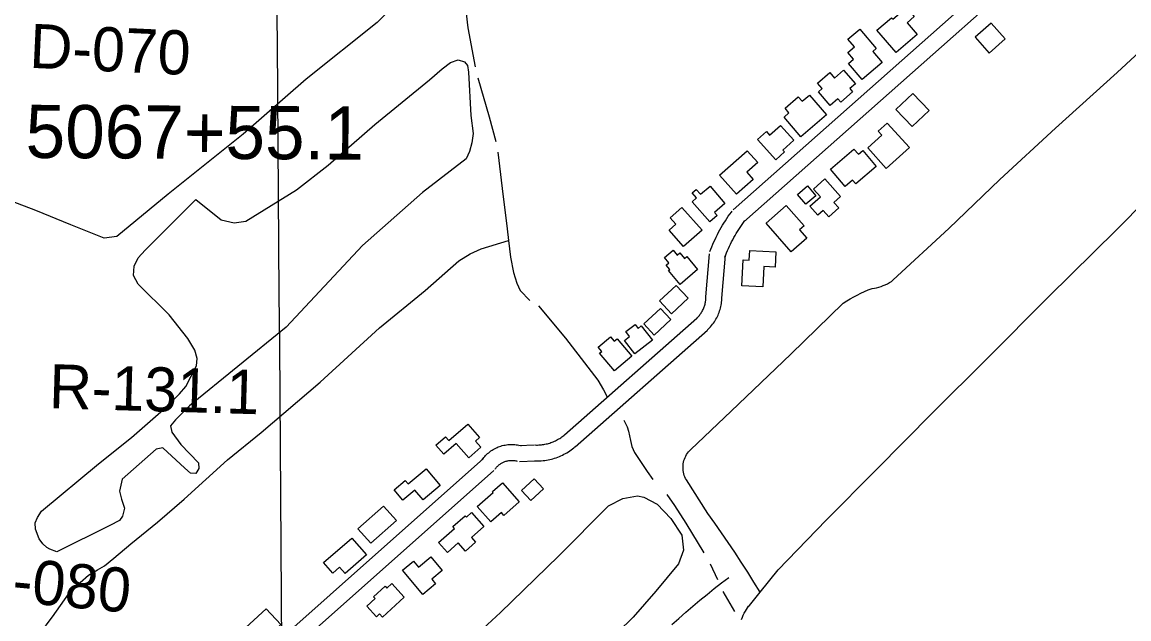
# Model space of a CAD drawing. Extents: x 3535183 to 3573198, y 534952 to 560562.
# Drawn here: x 3554620 to 3556701, y 553117 to 554240 of the extents above; entities that cross this region are included whole.
import ezdxf

# ---------------------------------------------------------------- set-up
doc = ezdxf.new("R2010")
doc.units = 0
for name, color, linetype in [('V-BLDG-OTLN', 7, 'Continuous'), ('V-DTCH-CNTR', 7, 'Continuous'), ('V-GRID-MAJR', 7, 'Continuous'), ('V-RIVR-RANG-IDEN', 7, 'Continuous'), ('V-ROAD-CNTR', 7, 'Continuous'), ('V-SITE-VEGE', 7, 'Continuous'), ('V-SURV-IDEN', 7, 'Continuous'), ('V-TOPO-SHOR', 7, 'Continuous')]:
    doc.layers.add(name, color=color, linetype=linetype)

msp = doc.modelspace()

# ---------------------------------------------------------------- linework, layer by layer
at = {"layer": 'V-BLDG-OTLN'}
for points in [[(3556284.02, 554238.5), (3556302.765, 554216.926), (3556263.6550000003, 554182.938), (3556227.417, 554224.637), (3556254.639, 554248.2930000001), (3556257.267, 554245.273), (3556282.752, 554267.42), (3556297.615, 554250.313)], [(3556195.071, 554226.716), (3556226.058, 554190.589), (3556219.508, 554184.971), (3556237.309, 554164.215), (3556199.964, 554132.186), (3556174.102, 554162.341), (3556183.361, 554170.283), (3556172.812, 554182.581), (3556185.267, 554193.264), (3556172.8910000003, 554207.694)], [(3556442.0900774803, 554238.2794971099), (3556412.156137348, 554211.7455501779), (3556438.689084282, 554181.812610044), (3556468.6230244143, 554208.345556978)], [(3556153.8310000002, 554095.8420000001), (3556139.536, 554083.345), (3556117.358, 554108.714), (3556124.6750000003, 554115.1140000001), (3556115.722, 554125.354), (3556138.594, 554145.353), (3556147.816, 554134.806), (3556164.697, 554149.5650000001), (3556186.92, 554124.15), (3556176.34, 554114.897), (3556181.698, 554108.773), (3556159.498, 554089.362)], [(3556100.503, 554102.8200000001), (3556132.529, 554065.393), (3556084.5100000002, 554024.306), (3556052.768, 554061.399), (3556062.0500000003, 554069.341), (3556054.615, 554078.029), (3556079.669, 554099.465), (3556086.818, 554091.109)], [(3556325.482, 554073.56), (3556293.775, 554043.358), (3556263.159, 554075.502), (3556294.864, 554105.701)], [(3556045.93, 554045.808), (3556071.186, 554017.738), (3556050.6750000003, 553999.283), (3556053.815, 553995.7980000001), (3556037.482, 553981.099), (3556003.0470000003, 554019.372), (3556019.517, 554034.193), (3556025.558, 554027.478)], [(3556246.947, 554050.082), (3556288.347, 554003.8150000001), (3556244.705, 553964.764), (3556210.071, 554003.4670000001), (3556236.588, 554027.1950000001), (3556229.824, 554034.757)], [(3555931.563, 553952.067), (3555983.546, 553998.153), (3556003.542, 553975.596), (3555983.089, 553957.463), (3555994.863, 553944.184), (3555963.336, 553916.231)], [(3556200.691, 553998.278), (3556226.211, 553968.387), (3556187.827, 553935.6190000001), (3556181.79, 553942.693), (3556167.786, 553930.7390000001), (3556139.91, 553963.392), (3556184.295, 554001.284), (3556192.691, 553991.446)], [(3555913.6350000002, 553931.501), (3555941.756, 553899.013), (3555921.952, 553881.871), (3555926.978, 553876.067), (3555913.144, 553864.093), (3555880.185, 553902.169), (3555888.23, 553909.13), (3555880.1010000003, 553918.52), (3555887.873, 553925.25), (3555895.815, 553916.077)], [(3556112.59, 553913.142), (3556093.878, 553897.258), (3556078.059, 553915.897), (3556096.771, 553931.781)], [(3556108.16, 553925.885), (3556129.732, 553944.89), (3556158.877, 553911.8150000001), (3556146.507, 553900.916), (3556155.852, 553890.309), (3556137.029, 553873.726), (3556126.631, 553885.525), (3556116.434, 553876.54), (3556101.244, 553893.78), (3556121.061, 553911.24)], [(3555860.8680000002, 553891.139), (3555898.6210000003, 553848.514), (3555863.92, 553817.777), (3555836.585, 553848.638), (3555849.129, 553859.747), (3555838.7090000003, 553871.511)], [(3556018.994, 553861.557), (3556056.684, 553894.884), (3556090.603, 553856.529), (3556082.102, 553849.011), (3556095.614, 553833.731), (3556066.4280000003, 553807.92)], [(3555869.794, 553798.807), (3555890.364, 553774.376), (3555857.282, 553746.523), (3555835.4450000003, 553772.461), (3555838.115, 553774.71), (3555831.205, 553782.9180000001), (3555836.268, 553787.18), (3555827.773, 553797.273), (3555844.239, 553811.135), (3555852.076, 553801.825), (3555856.953, 553805.932), (3555865.79, 553795.436)], [(3555988.348, 553810.028), (3556037.252, 553807.73), (3556035.911, 553779.1680000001), (3556014.872, 553780.157), (3556013.078, 553741.95), (3555973.6350000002, 553743.803), (3555975.927, 553792.554), (3555987.502, 553792.009)], [(3555841.537, 553691.356), (3555818.886, 553715.527), (3555850, 553744.684), (3555872.651, 553720.514)], [(3555808.54, 553651.2710000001), (3555789.012, 553672.322), (3555820.398, 553701.434), (3555839.926, 553680.385)], [(3555772.366, 553615.7930000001), (3555752.576, 553641.004), (3555762.325, 553648.657), (3555755.247, 553657.6730000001), (3555772.735, 553671.4), (3555778.67, 553663.837), (3555784.382, 553668.3200000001), (3555805.3140000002, 553641.653)], [(3555739.0470000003, 553644.375), (3555766.648, 553611.365), (3555733.8370000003, 553583.93), (3555706.132, 553617.067), (3555710.072, 553620.36), (3555703.432, 553628.302), (3555726.661, 553647.724), (3555733.403, 553639.656)], [(3555422.596, 553452.596), (3555458.1720000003, 553483.554), (3555480.225, 553458.212), (3555472.736, 553451.693), (3555482.728, 553440.212), (3555460.007, 553420.443), (3555436.506, 553447.452), (3555413.077, 553427.066), (3555398.446, 553443.88), (3555416.508, 553459.594)], [(3555346.323, 553371.358), (3555379.7600000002, 553399.5430000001), (3555406.315, 553368.0380000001), (3555374.251, 553341.015), (3555358.6580000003, 553359.517), (3555336.199, 553340.589), (3555319.772, 553360.082), (3555340.84, 553377.863)], [(3555555.075, 553337.218), (3555526.24, 553311.976), (3555521.4590000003, 553317.438), (3555501.483, 553299.951), (3555476.18, 553328.856), (3555506.1240000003, 553355.073), (3555504.535, 553356.887), (3555523.401, 553373.402)], [(3555600.549, 553361.696), (3555576.911, 553339.837), (3555559.403, 553358.7710000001), (3555583.041, 553380.63)], [(3555324.014, 553302.482), (3555275.714, 553259.558), (3555251.646, 553286.639), (3555299.9560000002, 553329.554)], [(3555403.319, 553260.912), (3555433.455, 553287.456), (3555430.336, 553290.995), (3555453.339, 553311.258), (3555455.7430000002, 553308.528), (3555465.482, 553317.105), (3555488.591, 553290.872), (3555465.309, 553270.363), (3555472.975, 553261.661), (3555453.89, 553244.849), (3555440.367, 553260.203), (3555419.858, 553242.138)], [(3555187.123, 553223.355), (3555240.359, 553269.403), (3555267.915, 553237.544), (3555227.578, 553202.654), (3555217.223, 553214.627), (3555204.325, 553203.469)], [(3555365.924, 553214.604), (3555389.046, 553233.8640000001), (3555410.419, 553208.206), (3555390.6, 553191.702), (3555397.867, 553182.975), (3555373.727, 553162.87), (3555335.563, 553208.688), (3555356.397, 553226.042)], [(3555338.94, 553158.1680000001), (3555297.898, 553120.6950000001), (3555292.3170000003, 553126.807), (3555286.365, 553121.373), (3555268.3140000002, 553141.143), (3555284.137, 553155.589), (3555281.268, 553158.735), (3555302.9930000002, 553178.572), (3555306.037, 553175.238), (3555315.482, 553183.862)], [(3555052.648, 553056.888), (3555025.565, 553086.33), (3555079.554, 553135.996), (3555106.637, 553106.554)]]:
    msp.add_lwpolyline(points, close=True, dxfattribs=at)
at = {"layer": 'V-DTCH-CNTR'}
for points in [[(3555986.251, 553140.93), (3555987.644, 553142.748), (3556007.823, 553167.609), (3556041.703, 553209.343), (3556131.9990000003, 553302.99), (3556225.414, 553397.03), (3556333.2290000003, 553505.897), (3556433.262, 553605.7930000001), (3556550.029, 553722.856), (3556677.699, 553849.286), (3556791.3510000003, 553964.006), (3556875.81, 554051.8), (3556968.443, 554145.84), (3557082.875, 554262.511), (3557214.992, 554385.362), (3557325.5300000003, 554497.351), (3557493.6750000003, 554666.313), (3557606.16, 554781.421), (3557708.529, 554882.876), (3557851.377, 555024.526), (3557973.2, 555149.78), (3558100.09, 555276.209)], [(3556007.823, 553167.609), (3555996.221, 553186.524), (3555984.4280000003, 553205.323), (3555972.454, 553224.005), (3555960.291, 553242.568), (3555947.9450000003, 553261.006), (3555935.418, 553279.321), (3555922.708, 553297.513), (3555909.818, 553315.577), (3555869.208, 553378.657), (3555867.719, 553381.416), (3555866.421, 553384.269), (3555865.315, 553387.202), (3555864.411, 553390.204), (3555863.711, 553393.26), (3555863.219, 553396.354), (3555862.937, 553399.477), (3555862.863, 553402.611), (3555863.002, 553405.7440000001), (3555863.353, 553408.859), (3555863.912, 553411.9450000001), (3555864.6780000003, 553414.987), (3555865.646, 553417.969), (3555866.8140000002, 553420.879), (3555868.174, 553423.705), (3555869.722, 553426.433), (3555871.45, 553429.05), (3555873.3510000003, 553431.545), (3555875.413, 553433.906), (3555877.631, 553436.1240000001), (3555953.223, 553507.759), (3556065.715, 553615.072), (3556164.1920000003, 553711.457), (3556170.614, 553715.512), (3556177.145, 553719.3910000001), (3556183.781, 553723.0920000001), (3556190.512, 553726.608), (3556197.338, 553729.9400000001), (3556204.254, 553733.086), (3556211.25, 553736.041), (3556218.326, 553738.804), (3556222.613, 553739.447), (3556226.856, 553740.314), (3556231.051, 553741.399), (3556235.183, 553742.702), (3556239.2430000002, 553744.2170000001), (3556243.218, 553745.944), (3556247.097, 553747.873), (3556250.869, 553750.001), (3556254.5270000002, 553752.323), (3556258.058, 553754.834), (3556362.77, 553851.6140000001), (3556458.524, 553943.709), (3556563.234, 554040.491), (3556679.237, 554145.469), (3556797.5700000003, 554254.738)]]:
    msp.add_lwpolyline(points, dxfattribs=at)
at = {"layer": 'V-GRID-MAJR'}
msp.add_spline([(3555204.1780000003, 540472.404), (3555158.363, 546529.794), (3555112.522, 552590.651), (3555066.681, 558651.524), (3555066.6550000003, 558654.975)], degree=3, dxfattribs=at)
at = {"layer": 'V-ROAD-CNTR'}
for points in [[(3555957.20604725, 553886.76520014), (3556782.72439621, 554618.5097366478), (3557406.0441495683, 555171.660630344)], [(3555977.1060074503, 553864.31524504), (3556802.6303563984, 554596.0657815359), (3557427.46810672, 555150.5646725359)], [(3555913.4671347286, 553808.1393573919), (3555915.1961312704, 553812.7153482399), (3555917.0491275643, 553817.3783389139), (3555918.978123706, 553822.0073296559), (3555920.985119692, 553826.6053204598), (3555923.07111552, 553831.1703113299), (3555925.2321111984, 553835.6973022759), (3555927.468106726, 553840.186293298), (3555929.7791021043, 553844.638284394), (3555932.165097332, 553849.053275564), (3555934.62609241, 553853.42526682), (3555937.1580873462, 553857.756258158), (3555939.7640821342, 553862.0432495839), (3555942.4400767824, 553866.286241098), (3555945.1880712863, 553870.4842327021), (3555948.005065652, 553874.634224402), (3555950.8920598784, 553878.7372161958), (3555953.8260540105, 553882.7622081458), (3555955.1420513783, 553884.5222046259)], [(3555941.5310786, 553797.5353785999), (3555943.170075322, 553801.8733699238), (3555944.8370719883, 553806.0683615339), (3555946.574068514, 553810.2353532), (3555948.379064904, 553814.371344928), (3555950.2530611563, 553818.4743367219), (3555952.1980572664, 553822.5473285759), (3555954.210053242, 553826.5883204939), (3555956.2890490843, 553830.5943124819), (3555958.4350447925, 553834.563304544), (3555960.6480403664, 553838.4972966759), (3555962.9260358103, 553842.3922888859), (3555965.2700311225, 553846.2492811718), (3555967.6780263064, 553850.0662735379), (3555970.1500213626, 553853.842265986), (3555972.685016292, 553857.576258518), (3555975.2820110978, 553861.2672511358), (3555977.962005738, 553864.9422437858), (3555979.1700033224, 553866.5582405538)], [(3555905.9311498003, 553723.402526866), (3555912.549136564, 553804.0643655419)], [(3555935.8310900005, 553720.9485317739), (3555942.4490767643, 553801.6103704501)], [(3555888.359184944, 553682.8646079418), (3555889.869181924, 553684.296605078), (3555891.1511793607, 553685.601602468), (3555892.389176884, 553686.949599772), (3555893.579174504, 553688.3375969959), (3555894.7221722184, 553689.7665941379), (3555895.8131700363, 553691.231591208), (3555896.85616795, 553692.7355881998), (3555897.847165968, 553694.272585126), (3555898.7821640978, 553695.8415819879), (3555899.66616233, 553697.4465787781), (3555900.493160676, 553699.0755755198), (3555901.264159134, 553700.7335722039), (3555901.9791577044, 553702.4185688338), (3555902.635156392, 553704.123565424), (3555903.233155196, 553705.8525619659), (3555903.77115412, 553707.5995584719), (3555904.249153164, 553709.36555494), (3555904.667152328, 553711.1455513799), (3555905.023151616, 553712.9385477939), (3555905.318151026, 553714.746544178), (3555905.552150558, 553716.5595405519), (3555905.723150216, 553718.377536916), (3555905.83115, 553720.201533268), (3555905.8801499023, 553722.1535293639), (3555905.8811499, 553722.2875290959)], [(3555909.015143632, 553661.1066514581), (3555910.90113986, 553662.8986478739), (3555912.90113586, 553664.9336438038), (3555914.831132, 553667.0336396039), (3555916.689128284, 553669.2016352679), (3555918.470124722, 553671.4286308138), (3555920.1771213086, 553673.717626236), (3555921.8021180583, 553676.0636215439), (3555923.3471149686, 553678.462616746), (3555924.8101120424, 553680.91561184), (3555926.18610929, 553683.4106068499), (3555927.479106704, 553685.9576017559), (3555928.6821042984, 553688.54559658), (3555929.797102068, 553691.1725913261), (3555930.8211000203, 553693.8375859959), (3555931.753098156, 553696.534580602), (3555932.593096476, 553699.2615751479), (3555933.3390949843, 553702.01556964), (3555933.9910936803, 553704.79556408), (3555934.5470925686, 553707.594558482), (3555935.0080916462, 553710.4085528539), (3555935.372090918, 553713.2395471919), (3555935.639090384, 553716.0835415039), (3555935.809090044, 553718.933535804), (3555935.8780899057, 553721.663530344), (3555935.8810899, 553722.0635295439)], [(3555640.062681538, 553463.5380465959), (3555888.75618415, 553683.2276072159)], [(3555659.924641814, 553441.0540915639), (3555908.6181444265, 553660.743652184)], [(3555584.79179208, 553444.4450847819), (3555587.3217870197, 553444.3760849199), (3555589.630782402, 553444.3810849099), (3555591.942777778, 553444.4550847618), (3555594.2527731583, 553444.5940844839), (3555596.55676855, 553444.80108407), (3555598.8527639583, 553445.0750835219), (3555601.1387593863, 553445.4150828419), (3555603.4167548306, 553445.823082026), (3555605.6817503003, 553446.29608108), (3555607.9287458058, 553446.834080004), (3555610.160741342, 553447.4370787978), (3555612.375736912, 553448.1060774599), (3555614.5707325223, 553448.8400759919), (3555616.74172818, 553449.6350744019), (3555618.8877238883, 553450.4940726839), (3555621.009719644, 553451.415070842), (3555623.10171546, 553452.3970688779), (3555625.1667113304, 553453.4410667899), (3555627.199707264, 553454.5430645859), (3555629.198703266, 553455.704062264), (3555631.1666993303, 553456.924059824), (3555633.093695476, 553458.198057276), (3555634.9846916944, 553459.530054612), (3555636.8376879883, 553460.9160518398), (3555638.657684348, 553462.3630489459), (3555640.342680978, 553463.779046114)], [(3555485.328991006, 553416.657140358), (3555486.703988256, 553418.558136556), (3555488.332984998, 553420.633132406), (3555490.0419815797, 553422.6441283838), (3555491.8259780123, 553424.5841245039), (3555493.682974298, 553426.453120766), (3555495.6149704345, 553428.2511171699), (3555497.614966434, 553429.97111373), (3555499.678962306, 553431.61111045), (3555501.8049580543, 553433.1681073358), (3555503.9919536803, 553434.6451043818), (3555506.233949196, 553436.033101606), (3555508.5249446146, 553437.33109901), (3555510.8719399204, 553438.543096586), (3555513.2599351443, 553439.660094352), (3555515.6879302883, 553440.6830923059), (3555518.1579253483, 553441.6120904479), (3555520.6619203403, 553442.4430887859), (3555523.194915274, 553443.1760873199), (3555525.7539101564, 553443.8090860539), (3555528.334904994, 553444.3420849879), (3555530.9358997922, 553444.775084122), (3555533.553894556, 553445.105083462), (3555536.179889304, 553445.334083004), (3555538.8148840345, 553445.460082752), (3555541.4518787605, 553445.483082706), (3555544.0878734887, 553445.403082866), (3555546.715868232, 553445.22108323), (3555549.337862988, 553444.937083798), (3555551.9498577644, 553444.5500845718), (3555554.539852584, 553444.062085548), (3555557.058847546, 553443.4850867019), (3555558.565844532, 553443.089087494)], [(3555554.31185304, 553443.57608652), (3555583.948793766, 553444.444084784)], [(3555583.9837936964, 553414.4551447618), (3555586.9497877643, 553414.3761449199), (3555590.1387813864, 553414.3831449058), (3555593.322775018, 553414.483144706), (3555596.500768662, 553414.67614432), (3555599.672762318, 553414.96114375), (3555602.83675599, 553415.337142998), (3555605.988749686, 553415.8071420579), (3555609.124743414, 553416.3671409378), (3555612.24173718, 553417.0181396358), (3555615.340730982, 553417.7601381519), (3555618.4167248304, 553418.5931364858), (3555621.4657187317, 553419.5141346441), (3555624.4867126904, 553420.522132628), (3555627.477706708, 553421.6191304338), (3555630.4357007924, 553422.8021280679), (3555633.357694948, 553424.07112553), (3555636.243689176, 553425.4251228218), (3555639.084683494, 553426.8611199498), (3555641.885677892, 553428.379116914), (3555644.6406723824, 553429.9801137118), (3555647.3466669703, 553431.6581103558), (3555650.005661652, 553433.4161068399), (3555652.610656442, 553435.2501031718), (3555655.159651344, 553437.158099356), (3555657.643646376, 553439.1310954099), (3555659.644642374, 553440.8130920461)], [(3554296.937367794, 552388.4161968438), (3554309.633342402, 552388.4481967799), (3554320.9653197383, 552388.5861965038), (3554334.0322936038, 552393.30318707), (3555487.5139866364, 553419.0741355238)], [(3555509.634942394, 553399.0731755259), (3555510.6659403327, 553400.4981726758), (3555511.5709385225, 553401.6511703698), (3555512.519936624, 553402.7681681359), (3555513.513934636, 553403.8481659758), (3555514.550932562, 553404.8911638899), (3555515.6229304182, 553405.8891618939), (3555516.734928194, 553406.845159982), (3555517.884925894, 553407.759158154), (3555519.068923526, 553408.628156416), (3555520.283921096, 553409.447154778), (3555521.5319186, 553410.219153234), (3555522.8109160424, 553410.9451517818), (3555524.11191344, 553411.6171504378), (3555525.44191078, 553412.2381491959), (3555526.795908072, 553412.8091480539), (3555528.167905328, 553413.324147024), (3555529.559902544, 553413.7871460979), (3555530.968899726, 553414.1941452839), (3555532.3938968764, 553414.547144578), (3555533.8328939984, 553414.8441439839), (3555535.279891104, 553415.085143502), (3555536.7338881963, 553415.2691431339), (3555538.1978852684, 553415.39614288), (3555539.6628823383, 553415.46614274), (3555541.1298794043, 553415.4791427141), (3555542.595876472, 553415.435142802), (3555544.06187354, 553415.3331430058), (3555545.5218706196, 553415.175143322), (3555546.9698677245, 553414.9601437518), (3555548.41186484, 553414.688144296), (3555549.894861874, 553414.349144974), (3555550.935859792, 553414.0751455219)], [(3555555.189851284, 553413.5881464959), (3555584.8267920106, 553414.4561447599)], [(3554297.0133676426, 552358.4162568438), (3554309.8533419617, 552358.4482567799), (3554326.391308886, 552358.650256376), (3554349.6522623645, 552367.0472395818), (3555507.449946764, 553396.6561803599)], [(3555842.117, 553106.49), (3555854.98, 553118.219), (3555868.004, 553129.772), (3555881.18, 553141.147), (3555894.5130000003, 553152.341), (3555907.995, 553163.355), (3555921.622, 553174.187), (3555935.397, 553184.83), (3555949.315, 553195.2880000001)], [(3555973.048, 553116.079), (3555974.541, 553120.181), (3555976.238, 553124.201), (3555978.139, 553128.132), (3555980.234, 553131.961), (3555986.251, 553140.93)]]:
    msp.add_lwpolyline(points, dxfattribs=at)
at = {"layer": 'V-SITE-VEGE'}
for points in [[(3555142.62, 555339.3960000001), (3555235.069, 555210.9130000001), (3555332.97, 555085.157), (3555398.125, 554980.414), (3555464.863, 554849.959), (3555471.505, 554827.367), (3555482.085, 554758.809), (3555480.174, 554718.678), (3555473.614, 554645.427), (3555462.788, 554551.9130000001), (3555429.031, 554396.825), (3555424.759, 554382.405), (3555413.864, 554366.811), (3555392.845, 554343.028), (3555288.137, 554239.303), (3555154.599, 554132.432), (3555035.864, 554029.086), (3554894.929, 553916.366), (3554798.378, 553836.803), (3554774.617, 553833.666), (3554712.2600000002, 553858.934), (3554646.392, 553885.367), (3554598.457, 553904.027)], [(3555364.912, 552986.5920000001), (3555519.645, 553129.496), (3555628.771, 553235.303), (3555722.694, 553329.782), (3555749.598, 553343.849), (3555777.287, 553348.556), (3555789.383, 553346.225), (3555814.358, 553332.985), (3555840.126, 553306.093), (3555860.438, 553274.906), (3555863.973, 553246.823), (3555854.245, 553220.681), (3555811.774, 553169.542), (3555768.907, 553120.746), (3555681.22, 553034.851)]]:
    msp.add_lwpolyline(points, dxfattribs=at)
msp.add_lwpolyline([(3554947.034, 553906.367), (3554994.65, 553868.215), (3555019.222, 553862.397), (3555041.054, 553865.545), (3555136.1180000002, 553924.541), (3555195.719, 553971.017), (3555283.742, 554047.161), (3555386.185, 554131.512), (3555410.333, 554151.818), (3555425.914, 554164.3150000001), (3555440.3340000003, 554169.011), (3555452.036, 554165.517), (3555457.894, 554158.507), (3555459.862, 554145.6410000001), (3555463.862, 554064.545), (3555468.193, 554030.237), (3555465.877, 554012.687), (3555461.607, 553996.697), (3555454.998, 553982.651), (3555373.1950000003, 553919.383), (3555260.634, 553819.811), (3555116.56, 553666.393), (3554935.045, 553518.386), (3554908.569, 553491.449), (3554899.613, 553480.5210000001), (3554901.966, 553468.435), (3554918.762, 553445.453), (3554951.948, 553410.79), (3554952.74, 553400.264), (3554946.9050000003, 553390.509), (3554936.7660000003, 553391.275), (3554926.616, 553401.011), (3554885.236, 553439.172), (3554872.764, 553436.425), (3554861.856, 553427.447), (3554808.497, 553380.197), (3554803.457, 553357.577), (3554807.375, 553342.764), (3554812.856, 553325.6140000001), (3554808.977, 553310.404), (3554803.529, 553302.207), (3554785.214, 553292.826), (3554685.847, 553243.573), (3554672.5840000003, 553248.234), (3554667.122, 553251.345), (3554659.315, 553258.745), (3554652.284, 553268.094), (3554645.632, 553286.022), (3554644.838, 553298.107), (3554649.114, 553308.251), (3554656.896, 553319.96), (3554764.011, 553408.9940000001), (3554825.944, 553458.593), (3554886.315, 553511.306), (3554916.302, 553540.589), (3554928.3710000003, 553554.251), (3554948.21, 553593.267), (3554949.748, 553607.304), (3554945.052, 553622.8960000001), (3554932.1580000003, 553644.715), (3554897.008, 553689.511), (3554838.447, 553747.144), (3554829.85, 553763.509), (3554830.997, 553781.057), (3554838.386, 553796.273), (3554852.015, 553811.109)], close=True, dxfattribs=at)
at = {"layer": 'V-TOPO-SHOR'}
for p, q in [((3555913.858, 553220.546), (3555927.529, 553191.321)), ((3555937.685, 553168.719), (3555959.938, 553130.925))]:
    msp.add_line(p, q, dxfattribs=at)
for points in [[(3555443.8850000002, 554361.15), (3555445.856, 554338.151), (3555458.426, 554229.011), (3555472.1350000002, 554155.736)], [(3555477.221, 554135.08), (3555498.338, 554061.813), (3555510.853, 554015.434)], [(3555514.769, 553995.167), (3555523.0160000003, 553926.954), (3555532.0500000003, 553850.9450000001), (3555534.794, 553829.152), (3555538.722, 553797.934), (3555544.207, 553769.0920000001), (3555550.461, 553748.827), (3555556.7120000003, 553735.1900000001), (3555574.6580000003, 553716.493)], [(3554643.722, 553089.353), (3554656.575, 553096.7660000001), (3554665.529, 553105.737), (3554677.593, 553121.334), (3554707.56, 553163.832), (3554729.752, 553185.672), (3554745.327, 553199.324), (3554762.071, 553209.4720000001), (3554775.3140000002, 553217.277), (3554792.8340000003, 553231.318), (3554824.765, 553258.235), (3554874.994, 553299.193), (3554924.83, 553342.49), (3555006.594, 553416.207), (3555069.673, 553467.696), (3555180.64, 553562.873), (3555292.382, 553664.6730000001), (3555378.044, 553735.276), (3555441.5100000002, 553790.664), (3555462.9280000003, 553804.322), (3555483.182, 553813.689), (3555534.794, 553829.152)], [(3555591.431, 553705.983), (3555642.162, 553645.604), (3555683.921, 553590.676), (3555702.656, 553566.133), (3555713.197, 553548.211), (3555721.006, 553533.7930000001)], [(3555751.839, 553491.33), (3555757.698, 553478.471), (3555760.434, 553470.287), (3555763.9590000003, 553452.748), (3555766.697, 553441.447), (3555771.3850000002, 553430.535), (3555795.197, 553394.691), (3555806.125, 553379.4990000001)], [(3555832.268, 553351.454), (3555846.711, 553330.417), (3555868.182, 553297.3), (3555901.755, 553241.585)]]:
    msp.add_lwpolyline(points, dxfattribs=at)

# ---------------------------------------------------------------- texts
at = {"layer": 'V-RIVR-RANG-IDEN'}
for s, height, rotation, p in [('D-070', 83.00000000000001, 357.3743257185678, (3554633.24087587, 554154.1866392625)), ('R-131.1', 82.99999799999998, 358.3348083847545, (3554670.418, 553513.6680000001)), ('D-080', 83, 354.45632571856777, (3554519.971238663, 553157.6043150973))]:
    msp.add_text(s, height=height, rotation=rotation, dxfattribs=at).set_placement(p)
at = {"layer": 'V-SURV-IDEN'}
msp.add_text('5067+55.1', height=100, rotation=359.7010321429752, dxfattribs=at).set_placement((3554626.8692918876, 553984.5405088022))

doc.saveas('drawing.dxf')
